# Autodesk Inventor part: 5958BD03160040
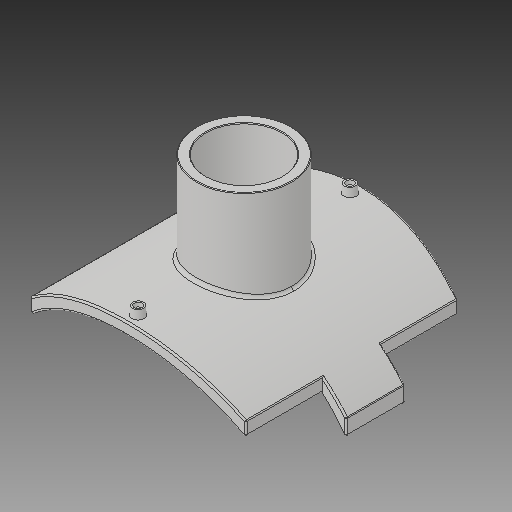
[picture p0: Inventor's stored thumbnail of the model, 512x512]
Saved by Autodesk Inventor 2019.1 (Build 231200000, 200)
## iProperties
Created: 2017-10
Part Number: 5958BD03160040
Material: Generic
Description: PLASSON BRANCH SADDLE 10''-16''IPS x 10''-14''DIPS
Document SubType Name: Modeling
Designer: KIM
Density: 1 g/cm^3
Appearance: Default
Author: KIM
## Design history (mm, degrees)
derived "5958B-1.ipt"
feature "Solid1::5958B-1.ipt"
tag "TaggingFeature1"
body "Solid1"
other parameters: "d0" = 404.6, "d1" = 14.986, "d2" = 274.32, "d3" = 299.974, "d4" = 0, "d5" = 304.8, "d6" = 74.9935, "d7" = 0, "d8" = 134.9883, "d10" = 0, "d11" = 2.023, "d12" = 227.9, "d13" = 14, "d14" = 134.9883, "d16" = 5 deg, "d18" = 4, "d19" = 14, "d20" = 0, "d21" = 3, "d22" = 0, "d23" = 327.268, "d24" = 121.3, "d25" = 16, "d26" = 97.04, "d28" = 0, "d29" = 9.6, "d31" = 0, "d32" = 87.4776, "d33" = 0, "d34" = 4.046, "d35" = 0.8092, "d_" = 404.6, "d_1" = 121.3, "B_" = 304.8, "H_" = 124.968, "L_" = 299.974, "x_" = 14.986, "D_" = 16, "H1" = 109.982
